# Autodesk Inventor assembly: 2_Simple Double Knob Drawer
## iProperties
Created: 2006-01
Part Number: 2_Simple Double Knob Drawer
Document SubType Name: Assembly
Designer: Demir Ali
Author: Demir Ali
